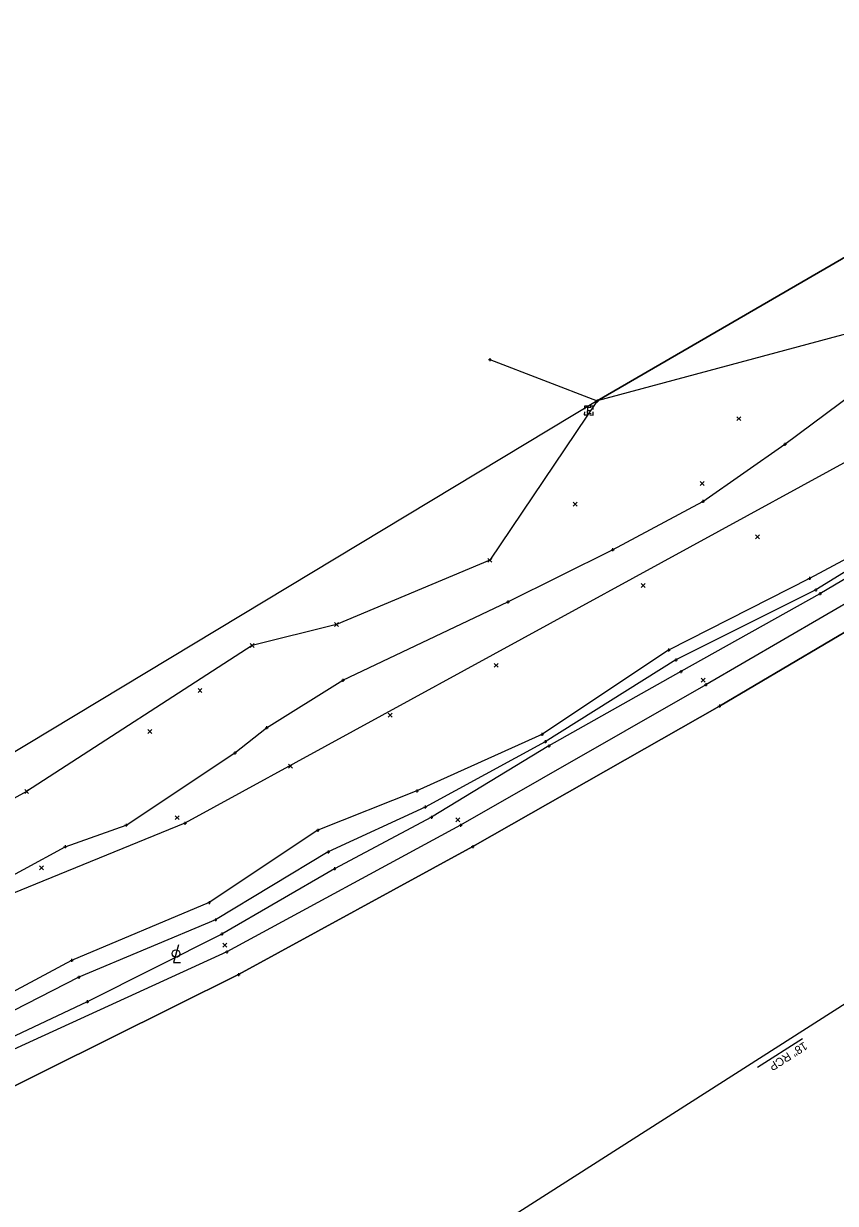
# Model space of a CAD drawing. Extents: x 142461 to 147261, y 511126 to 514697.
# Drawn here: x 146138.4 to 146413, y 514045.5 to 514444.2 of the extents above; entities that cross this region are included whole.
import ezdxf

# ---------------------------------------------------------------- set-up
doc = ezdxf.new("R2010")
doc.units = 0
for name, color, linetype in [('DR_X_Ditch', 7, 'Continuous'), ('DR_X_Storm_Sewer', 7, 'Continuous'), ('DR_X_Text', 7, 'Continuous'), ('LT_X_Poles', 7, 'Continuous'), ('PM_X_Surveyed_Line', 7, 'Continuous'), ('PV_X_EOP', 7, 'Continuous'), ('RD_X_Fence', 7, 'Continuous'), ('SV_X_Original_Ground', 7, 'Continuous'), ('SV_X_Random_Point', 7, 'Continuous'), ('SV_X_Shot_Marker', 7, 'Continuous'), ('SV_X_Toe_of_Slope', 7, 'Continuous'), ('SV_X_Top_of_Bank', 7, 'Continuous'), ('UT_X_Electric_Cells', 7, 'Continuous'), ('VG_X_Tree_Line_Lt', 7, 'Continuous')]:
    doc.layers.add(name, color=color, linetype=linetype)

msp = doc.modelspace()

# ---------------------------------------------------------------- linework, layer by layer
at = {"layer": 'DR_X_Ditch'}
msp.add_lwpolyline([(146972.34, 514593.46), (146929.62, 514568.11), (146890.14, 514544.2), (146843.47, 514516.97), (146803.26, 514492.13), (146758.98, 514467.66), (146720.48, 514443.67), (146687.05, 514425.75), (146643.71, 514397.16), (146592.68, 514366.15), (146552.17, 514341.71), (146515.69, 514319.43), (146477.06, 514294.98), (146443.78, 514275.87), (146406.32, 514252.85), (146359.05, 514229.18), (146314.83, 514201.54), (146274.19, 514179.48), (146241.44, 514164.3), (146203.29, 514141.37), (146157.06, 514121.98), (146117.23, 514101.58)], dxfattribs=at)
at = {"layer": 'DR_X_Storm_Sewer'}
msp.add_line((146602.71, 514231.89), (146186.88, 513966.72), dxfattribs=at)
at = {"layer": 'DR_X_Text'}
msp.add_line((146386.66, 514091.57), (146401.88, 514101.27), dxfattribs=at)
msp.add_line((146386.66, 514091.57), (146401.88, 514101.27), dxfattribs=at)
at = {"layer": 'LT_X_Poles'}
msp.add_lwpolyline([(146190.78, 514132.91), (146189.14, 514126.94), (146191.5, 514126.92)], dxfattribs=at)
msp.add_circle((146189.96, 514129.97), 1.3, dxfattribs=at)
at = {"layer": 'PM_X_Surveyed_Line'}
msp.add_lwpolyline([(146936.5, 514545.38), (146901.96, 514523.88), (146817.16, 514475.05), (146691.97, 514405.14), (146614.79, 514358.5), (146537.21, 514310.98), (146456.62, 514262.43), (146373.73, 514213.61), (146290.32, 514166.13), (146211.14, 514122.87), (146123.97, 514079.6), (146039.98, 514041.62), (145963.95, 514008.93), (145842.42, 513958.73), (145748.84, 513919.85), (145682.8, 513887.45), (145618.56, 513849.17)], dxfattribs=at)
at = {"layer": 'PV_X_EOP'}
for p, q in [((146452.24, 514269.11), (146369.12, 514220.8)), ((146369.12, 514220.8), (146286.22, 514173.31)), ((146286.22, 514173.31), (146207.13, 514130.54)), ((146207.13, 514130.54), (146119.47, 514090.47))]:
    msp.add_line(p, q, dxfattribs=at)
at = {"layer": 'RD_X_Fence'}
msp.add_lwpolyline([(146900.86, 514646.23), (146332.42, 514316.7), (145890.39, 514050.56), (145774.93, 514232.06), (145655.09, 514421.49), (144949.64, 513970.2), (144936.36, 513451.75), (144101.94, 512896.99), (144046.01, 512862.62), (143758.01, 512670.87), (143619.22, 512579.24), (143474.12, 512483.15), (143357.83, 512406.57), (143315.36, 512377.21)], dxfattribs=at)
at = {"layer": 'SV_X_Original_Ground'}
for points in [[(146764.79, 514555.47), (146687.58, 514514.51), (146654.76, 514494.88), (146609.54, 514466.88), (146561.33, 514427.46), (146475.78, 514376.04), (146418.4, 514339.85), (146332.42, 514316.7), (146296.13, 514262.85), (146244.27, 514241.18), (146215.75, 514234.07), (146139.46, 514184.74), (146098.44, 514162.17)], [(146123.97, 514079.6), (146211.14, 514122.87), (146290.32, 514166.13), (146373.73, 514213.61), (146456.62, 514262.43), (146537.21, 514310.98), (146614.79, 514358.5), (146691.97, 514405.14), (146817.16, 514475.05)]]:
    msp.add_lwpolyline(points, dxfattribs=at)
at = {"layer": 'SV_X_Random_Point'}
for p, q in [((146379.68, 514310.05), (146381.01, 514311.39)), ((146379.68, 514311.39), (146381.01, 514310.05)), ((146367.21, 514288.1), (146368.55, 514289.44)), ((146367.21, 514289.44), (146368.55, 514288.1)), ((146324.26, 514281.15), (146325.59, 514282.49)), ((146324.26, 514282.49), (146325.59, 514281.15)), ((146385.97, 514270.1), (146387.3, 514271.44)), ((146385.97, 514271.44), (146387.3, 514270.1)), ((146295.46, 514262.18), (146296.8, 514263.51)), ((146295.46, 514263.51), (146296.8, 514262.18)), ((146347.28, 514253.64), (146348.62, 514254.97)), ((146347.28, 514254.97), (146348.62, 514253.64)), ((146243.6, 514240.51), (146244.93, 514241.85)), ((146243.6, 514241.85), (146244.93, 514240.51)), ((146215.09, 514233.4), (146216.42, 514234.74)), ((146215.09, 514234.74), (146216.42, 514233.4)), ((146297.6, 514226.71), (146298.93, 514228.04)), ((146297.6, 514228.04), (146298.93, 514226.71)), ((146197.42, 514218.22), (146198.76, 514219.56)), ((146197.42, 514219.56), (146198.76, 514218.22)), ((146367.54, 514221.67), (146368.89, 514222.99)), ((146367.56, 514223), (146368.88, 514221.65)), ((146261.74, 514209.89), (146263.08, 514211.23)), ((146261.74, 514211.23), (146263.08, 514209.89)), ((146180.43, 514204.36), (146181.77, 514205.69)), ((146180.43, 514205.69), (146181.77, 514204.36)), ((146228.05, 514192.58), (146229.38, 514193.92)), ((146228.05, 514193.92), (146229.38, 514192.58)), ((146138.79, 514184.07), (146140.13, 514185.41)), ((146138.79, 514185.41), (146140.13, 514184.07)), ((146189.74, 514175.22), (146191.07, 514176.56)), ((146189.74, 514176.56), (146191.07, 514175.22)), ((146284.59, 514174.46), (146285.94, 514175.78)), ((146284.6, 514175.79), (146285.92, 514174.44)), ((146143.83, 514158.28), (146145.16, 514159.61)), ((146143.83, 514159.61), (146145.16, 514158.28)), ((146205.79, 514132.13), (146207.14, 514133.45)), ((146205.8, 514133.47), (146207.12, 514132.12))]:
    msp.add_line(p, q, dxfattribs=at)
at = {"layer": 'SV_X_Shot_Marker'}
for p, q in [((146296.12, 514331.16), (146296.11, 514330.16)), ((146295.61, 514330.67), (146296.61, 514330.66)), ((146296.11, 514330.66), (146296.11, 514330.66)), ((146331.92, 514316.71), (146332.92, 514316.7)), ((146331.92, 514316.71), (146332.92, 514316.7)), ((146332.43, 514317.2), (146332.42, 514316.2)), ((146332.43, 514317.2), (146332.42, 514316.2)), ((146332.42, 514316.7), (146332.42, 514316.7)), ((146332.42, 514316.7), (146332.42, 514316.7)), ((146395.41, 514302.05), (146396.41, 514302.05)), ((146395.91, 514302.55), (146395.91, 514301.55)), ((146395.91, 514302.05), (146395.91, 514302.05)), ((146368.17, 514283.24), (146368.17, 514282.24)), ((146367.67, 514282.74), (146368.67, 514282.74)), ((146368.17, 514282.74), (146368.17, 514282.74)), ((146337.62, 514266.94), (146337.62, 514265.94)), ((146337.12, 514266.44), (146338.12, 514266.44)), ((146337.62, 514266.44), (146337.62, 514266.44)), ((146403.7, 514256.75), (146404.7, 514256.75)), ((146404.2, 514257.25), (146404.2, 514256.25)), ((146404.2, 514256.75), (146404.2, 514256.75)), ((146405.82, 514252.85), (146406.82, 514252.85)), ((146406.32, 514253.35), (146406.32, 514252.35)), ((146406.32, 514252.85), (146406.32, 514252.85)), ((146407.22, 514251.54), (146408.22, 514251.54)), ((146407.72, 514252.04), (146407.72, 514251.04)), ((146407.72, 514251.54), (146407.72, 514251.54)), ((146301.72, 514248.8), (146302.72, 514248.8)), ((146302.22, 514249.3), (146302.22, 514248.3)), ((146302.22, 514248.8), (146302.22, 514248.8)), ((146356.07, 514232.52), (146357.07, 514232.52)), ((146356.57, 514233.02), (146356.57, 514232.02)), ((146356.57, 514232.52), (146356.57, 514232.52)), ((146358.55, 514229.18), (146359.55, 514229.18)), ((146359.05, 514229.68), (146359.05, 514228.68)), ((146359.05, 514229.18), (146359.05, 514229.18)), ((146360.24, 514225.24), (146361.24, 514225.24)), ((146360.74, 514225.74), (146360.74, 514224.74)), ((146360.74, 514225.24), (146360.74, 514225.24)), ((146245.94, 514222.32), (146246.94, 514222.32)), ((146246.44, 514222.82), (146246.44, 514221.82)), ((146246.44, 514222.32), (146246.44, 514222.32)), ((146368.62, 514220.81), (146369.62, 514220.8)), ((146369.13, 514221.3), (146369.12, 514220.3)), ((146369.12, 514220.8), (146369.12, 514220.8)), ((146373.23, 514213.62), (146374.23, 514213.61)), ((146373.73, 514214.11), (146373.72, 514213.11)), ((146373.73, 514213.61), (146373.73, 514213.61)), ((146220.12, 514206.29), (146221.12, 514206.29)), ((146220.62, 514206.79), (146220.62, 514205.79)), ((146220.62, 514206.29), (146220.62, 514206.29)), ((146313.21, 514204.04), (146314.21, 514204.04)), ((146313.71, 514204.54), (146313.71, 514203.54)), ((146313.71, 514204.04), (146313.71, 514204.04)), ((146314.33, 514201.54), (146315.33, 514201.54)), ((146314.83, 514202.04), (146314.83, 514201.04)), ((146314.83, 514201.54), (146314.83, 514201.54)), ((146315.61, 514200.12), (146316.61, 514200.12)), ((146316.11, 514200.62), (146316.11, 514199.62)), ((146316.11, 514200.12), (146316.11, 514200.12)), ((146209.42, 514197.78), (146210.42, 514197.78)), ((146209.92, 514198.28), (146209.92, 514197.28)), ((146209.92, 514197.78), (146209.92, 514197.78)), ((146270.97, 514184.93), (146271.97, 514184.93)), ((146271.47, 514185.43), (146271.47, 514184.43)), ((146271.47, 514184.93), (146271.47, 514184.93)), ((146273.69, 514179.48), (146274.69, 514179.48)), ((146274.19, 514179.98), (146274.19, 514178.98)), ((146274.19, 514179.48), (146274.19, 514179.48)), ((146275.84, 514176.03), (146276.84, 514176.03)), ((146276.34, 514176.53), (146276.34, 514175.53)), ((146276.34, 514176.03), (146276.34, 514176.03)), ((146172.57, 514173.35), (146173.57, 514173.35)), ((146173.07, 514173.85), (146173.07, 514172.85)), ((146173.07, 514173.35), (146173.07, 514173.35)), ((146192.48, 514174.03), (146193.48, 514174.02)), ((146192.99, 514174.52), (146192.98, 514173.52)), ((146192.98, 514174.02), (146192.98, 514174.02)), ((146237.41, 514171.61), (146238.41, 514171.61)), ((146237.91, 514172.11), (146237.91, 514171.11)), ((146237.91, 514171.61), (146237.91, 514171.61)), ((146285.72, 514173.32), (146286.72, 514173.31)), ((146286.23, 514173.81), (146286.22, 514172.81)), ((146286.22, 514173.31), (146286.22, 514173.31)), ((146151.94, 514166.06), (146152.94, 514166.06)), ((146152.44, 514166.56), (146152.44, 514165.56)), ((146152.44, 514166.06), (146152.44, 514166.06)), ((146240.94, 514164.3), (146241.94, 514164.3)), ((146241.44, 514164.8), (146241.44, 514163.8)), ((146241.44, 514164.3), (146241.44, 514164.3)), ((146289.82, 514166.14), (146290.82, 514166.13)), ((146290.32, 514166.63), (146290.31, 514165.63)), ((146290.32, 514166.13), (146290.32, 514166.13)), ((146243.07, 514158.61), (146244.07, 514158.61)), ((146243.57, 514159.11), (146243.57, 514158.11)), ((146243.57, 514158.61), (146243.57, 514158.61)), ((146201.18, 514147.69), (146201.18, 514146.69)), ((146200.68, 514147.19), (146201.68, 514147.19)), ((146201.18, 514147.19), (146201.18, 514147.19)), ((146202.79, 514141.37), (146203.79, 514141.37)), ((146203.29, 514141.87), (146203.29, 514140.87)), ((146203.29, 514141.37), (146203.29, 514141.37)), ((146204.94, 514136.54), (146205.94, 514136.54)), ((146205.44, 514137.04), (146205.44, 514136.04)), ((146205.44, 514136.54), (146205.44, 514136.54)), ((146154.16, 514127.64), (146155.16, 514127.64)), ((146154.66, 514128.14), (146154.66, 514127.14)), ((146154.66, 514127.64), (146154.66, 514127.64)), ((146206.63, 514130.55), (146207.63, 514130.54)), ((146207.14, 514131.04), (146207.13, 514130.04)), ((146207.13, 514130.54), (146207.13, 514130.54)), ((146156.56, 514121.98), (146157.56, 514121.98)), ((146157.06, 514122.48), (146157.06, 514121.48)), ((146157.06, 514121.98), (146157.06, 514121.98)), ((146210.64, 514122.87), (146211.64, 514122.86)), ((146211.15, 514123.37), (146211.14, 514122.37)), ((146211.14, 514122.87), (146211.14, 514122.87)), ((146159.47, 514113.67), (146160.47, 514113.67)), ((146159.97, 514114.17), (146159.97, 514113.17)), ((146159.97, 514113.67), (146159.97, 514113.67))]:
    msp.add_line(p, q, dxfattribs=at)
at = {"layer": 'SV_X_Toe_of_Slope'}
msp.add_lwpolyline([(146970.6, 514596.2), (146927.77, 514571.57), (146889.17, 514547.24), (146841.58, 514521.63), (146801.56, 514496.04), (146755.27, 514471.98), (146717.39, 514449.03), (146685.13, 514429.62), (146641.62, 514400.83), (146591.57, 514368.49), (146551.05, 514344.21), (146513.05, 514323.31), (146475.91, 514296.65), (146442.74, 514277.28), (146404.2, 514256.75), (146356.57, 514232.52), (146313.71, 514204.04), (146271.47, 514184.93), (146237.91, 514171.61), (146201.18, 514147.19), (146154.66, 514127.64), (146115.64, 514106.77)], dxfattribs=at)
at = {"layer": 'SV_X_Top_of_Bank'}
for points in [[(146110.05, 514143.01), (146152.44, 514166.06), (146173.07, 514173.35), (146209.92, 514197.78), (146220.62, 514206.29), (146246.44, 514222.32), (146302.22, 514248.8), (146337.62, 514266.44), (146368.17, 514282.74), (146395.91, 514302.05), (146432.82, 514329.56), (146480.97, 514359.22), (146527.7, 514388.82), (146558.29, 514415.59), (146612, 514450.74), (146657.74, 514482.92), (146689.43, 514508.5), (146727.89, 514529.91), (146764.79, 514555.47), (146807.06, 514577.35), (146848.65, 514601.59), (146910.75, 514629.75)], [(146977.31, 514587.49), (146933.53, 514561.2), (146894.23, 514537.47), (146847.45, 514510.07), (146807.46, 514485.33), (146762.55, 514460.95), (146723.94, 514439.52), (146691.01, 514419.15), (146646.91, 514393.1), (146595.15, 514362.87), (146554.48, 514338.98), (146518.1, 514316.46), (146478.28, 514292.87), (146445.52, 514273.79), (146407.72, 514251.54), (146360.74, 514225.24), (146316.11, 514200.12), (146276.34, 514176.03), (146243.57, 514158.61), (146205.44, 514136.54), (146159.97, 514113.67), (146119.4, 514094.6)]]:
    msp.add_lwpolyline(points, dxfattribs=at)
at = {"layer": 'UT_X_Electric_Cells'}
for p, q in [((146329.08, 514313.47), (146330.08, 514313.46)), ((146329.58, 514313.47), (146329.58, 514313.47))]:
    msp.add_line(p, q, dxfattribs=at)
for points in [[(146329.19, 514314.97), (146328.09, 514314.98), (146328.08, 514313.88)], [(146331.08, 514313.85), (146331.09, 514314.95), (146329.99, 514314.96)], [(146328.07, 514313.08), (146328.06, 514311.98), (146329.16, 514311.97)], [(146330.34, 514314.46), (146329.09, 514314.47), (146329.07, 514312.47), (146330.32, 514312.46)], [(146329.96, 514311.96), (146331.06, 514311.95), (146331.07, 514313.05)]]:
    msp.add_lwpolyline(points, dxfattribs=at)
at = {"layer": 'VG_X_Tree_Line_Lt'}
for points in [[(146296.11, 514330.66), (146332.42, 514316.7), (146900.86, 514646.22)], [(146913.71, 514577.37), (146591.44, 514391.6), (146192.98, 514174.02), (145890.39, 514050.56)]]:
    msp.add_lwpolyline(points, dxfattribs=at)

# ---------------------------------------------------------------- texts
at = {"layer": 'DR_X_Text'}
msp.add_text('18" RCP', height=2.8, rotation=212.5248, dxfattribs=at).set_placement((146402.37, 514100.28))

doc.saveas('drawing.dxf')
